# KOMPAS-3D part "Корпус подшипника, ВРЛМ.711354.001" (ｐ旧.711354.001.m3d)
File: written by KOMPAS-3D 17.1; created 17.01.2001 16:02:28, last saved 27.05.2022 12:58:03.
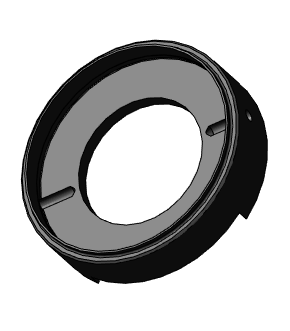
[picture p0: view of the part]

Document properties: Полное имя файла: D:\2023\Чертежи dwg cdw\ВРЛМ.711354.001.m3d

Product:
- Part/product: Корпус подшипника  | designation ВРЛМ.711354.001
    Материал: Сталь 40Х13 ГОСТ 5632-2014 (density 7650 kg/m3)
    Масса: 0.089348
    Полное имя файла: ВРЛМ.711354.001\ВРЛМ.711354.001.m3d
  - Body: Тело 1
      Масса: 0.089329

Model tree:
1. Фронтальная плоскость
2. Горизонтальная плоскость
3. Профильная плоскость
4. Начало координат
5. Эскиз:1
6. Операция вращения:1
     Угол 1 = 360
7. Смещенная плоскость:1
     Расстояние = 29
8. Эскиз:2
9. Вырезать элемент выдавливания:1
     Расстояние 2 = 10.3
10. Ось операции:1
11. Копия по концентрической сетке:1  (labels: Вырезать элемент выдавливания:1; Смещенная плоскость:1)  (2 pattern instances)
     N 1 = 1; Шаг 1 = 10; Шаг 2 = 360; Номер 1 = 1
12. Эскиз:3
13. Вырезать элемент выдавливания:2
     Расстояние 2 = 1.5; Угол 2 = 44
14. Копия по концентрической сетке:2  (labels: Вырезать элемент выдавливания:2)  (2 pattern instances)
     N 1 = 1; Шаг 1 = 10; Шаг 2 = 360; Номер 1 = 1
15. Эскиз:4
16. Вырезать элемент выдавливания:3
     Расстояние 2 = 4.5
17. Фаска:1
     Угол = 45; Длина 1 = 0.5; Длина 2 = 0.5
18. Скругление:1  (labels: Сталь 40Х13 ГОСТ 5632-2014; Сталь 40Х13 ГОСТ 5632-72; ВРЛМ.711354.001)
     Радиус = 0.5; Полуось 2 = 1; Коэффициент = 0.5; Хорда = 1

Referenced files in ВРЛМ.711354.001\: ВРЛМ.711354.001.m3d
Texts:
  ВРЛМ.711354.001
